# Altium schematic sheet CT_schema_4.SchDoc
size 207 x 169 mm
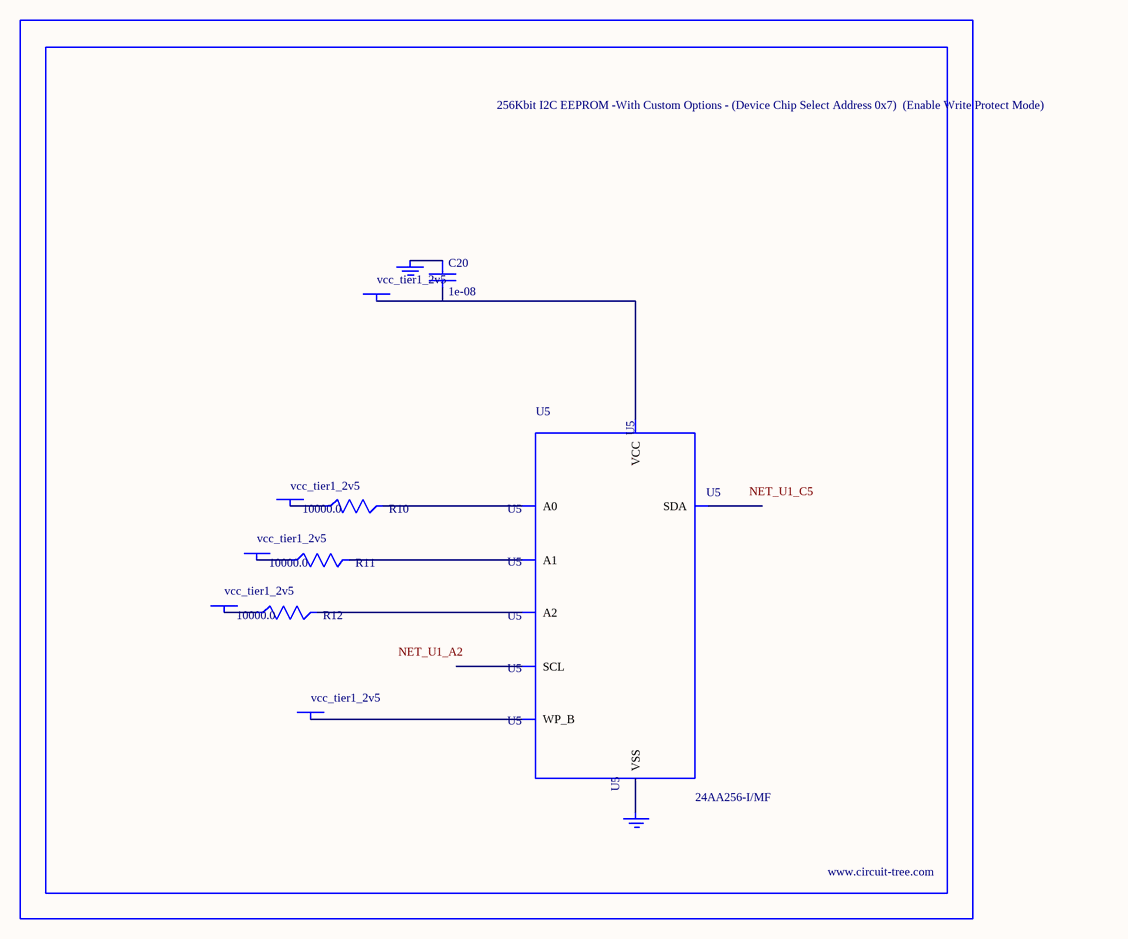
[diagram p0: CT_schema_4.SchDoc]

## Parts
BORDER3  (no value)
C20  1e-08  [C0402]
GND_INSTANCE_3_0  (no value)
GND_INSTANCE_3_1  (no value)
POWER_INSTANCE_3_0  vcc_tier1_2v5
POWER_INSTANCE_3_1  vcc_tier1_2v5
POWER_INSTANCE_3_2  vcc_tier1_2v5
POWER_INSTANCE_3_3  vcc_tier1_2v5
POWER_INSTANCE_3_4  vcc_tier1_2v5
R10  10000.0  [R0603]
R11  10000.0  [R0603]
R12  10000.0  [R0603]
U5  24AA256-I/MF  [DFN8-S]

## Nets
NetC20_1: C20.1 GND_INSTANCE_3_0.0(GND)
NetC20_2: C20.2 POWER_INSTANCE_3_4.0(PWR) U5.8(VCC)
NetGND_INSTANCE_3_1_0: GND_INSTANCE_3_1.0(GND) U5.4(VSS)
NetPOWER_INSTANCE_3_0_0: POWER_INSTANCE_3_0.0(PWR) R10.1
NetPOWER_INSTANCE_3_1_0: POWER_INSTANCE_3_1.0(PWR) R11.1
NetPOWER_INSTANCE_3_2_0: POWER_INSTANCE_3_2.0(PWR) R12.1
NetPOWER_INSTANCE_3_3_0: POWER_INSTANCE_3_3.0(PWR) U5.7(WP_B)
NetR10_2: R10.2 U5.1(A0)
NetR11_2: R11.2 U5.2(A1)
NetR12_2: R12.2 U5.3(A2)

Not connected (* = marked no-connect by the designer): U5 5(SDA) 6(SCL)

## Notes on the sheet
- Labels drawn without touching a wire or pin: NET_U1_A2, NET_U1_C5

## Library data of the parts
BORDER3 = BORDER_PAGE3
C20 = C0402C103K3RAC
GND_INSTANCE_3_0 GND_INSTANCE_3_1 = GND
POWER_INSTANCE_3_0-POWER_INSTANCE_3_4 = PWR
R10-R12 = RC0603JR-0710KL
